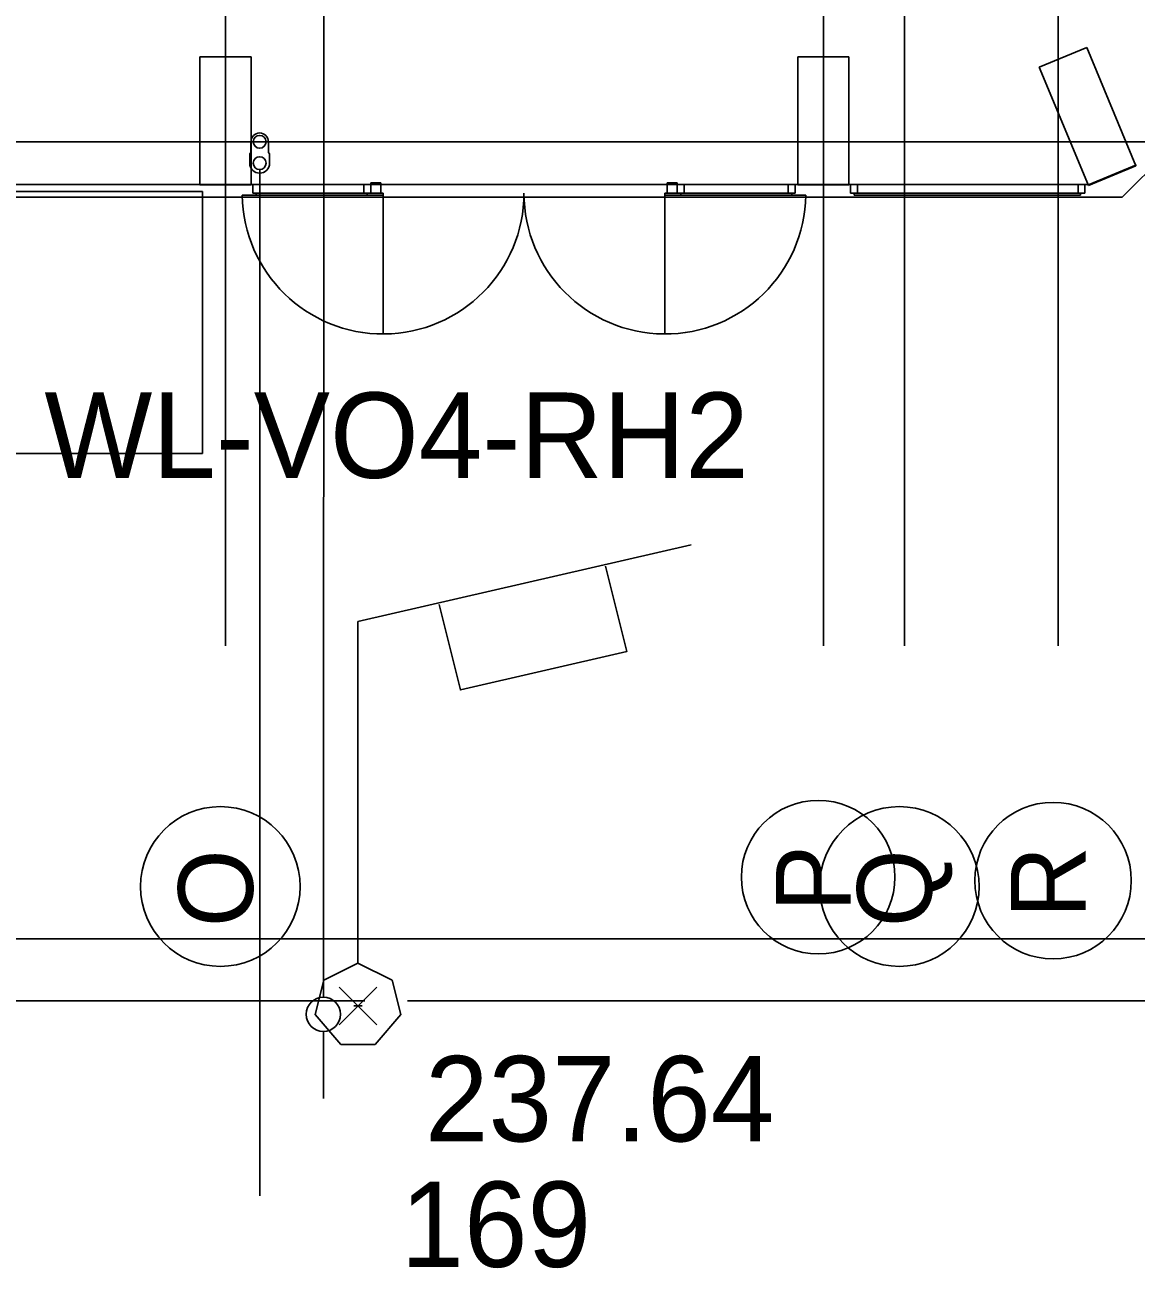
# Model space of a CAD drawing. Extents: x -264222 to -263592, y -1242345 to -1242048.
# Drawn here: x -263821.82 to -263808.81, y -1242253.99 to -1242239.44 of the extents above; entities that cross this region are included whole.
import ezdxf

# ---------------------------------------------------------------- set-up
doc = ezdxf.new("R2010")
doc.units = 0
for name, color, linetype in [('BOD_CISLO', 7, 'Continuous'), ('BOD_SYMBOL', 7, 'Continuous'), ('BOD_VYSKA', 7, 'Continuous'), ('HESCON_OSI_STAVBY_KFA', 7, 'Continuous'), ('KFA_2D_SITUACIA_DSP', 7, 'Continuous'), ('KFA_SO_62-1_VO_LAMPY_MERANE', 7, 'Continuous'), ('KFA_SO_62-1_VO_POPIS_LAMP_PROJEKT', 7, 'Continuous'), ('KFA_SO_62-1_VO_TRASA_KABLOV_PROJEKT', 7, 'Continuous')]:
    doc.layers.add(name, color=color, linetype=linetype)

msp = doc.modelspace()

# ---------------------------------------------------------------- linework, layer by layer
at = {"layer": 'BOD_SYMBOL'}
for p, q in [((-263818.138, -1242251.145), (-263817.696, -1242250.703)), ((-263817.696, -1242251.145), (-263818.138, -1242250.703))]:
    msp.add_line(p, q, dxfattribs=at)
at = {"layer": 'HESCON_OSI_STAVBY_KFA'}
for p, q in [((-263819.468, -1242083.237), (-263819.468, -1242246.707)), ((-263812.468, -1242083.237), (-263812.468, -1242246.707)), ((-263811.518, -1242083.237), (-263811.518, -1242246.707)), ((-263809.718, -1242083.237), (-263809.718, -1242246.707)), ((-263792.653, -1242240.807), (-263911.523, -1242240.807))]:
    msp.add_line(p, q, dxfattribs=at)
for centre, radius in [((-263819.528, -1242249.526), 0.935), ((-263812.528, -1242249.416), 0.899), ((-263811.578, -1242249.526), 0.935), ((-263809.778, -1242249.457), 0.916)]:
    msp.add_circle(centre, radius, dxfattribs=at)
at = {"layer": 'KFA_2D_SITUACIA_DSP'}
for p, q in [((-263818.318, -1242235.757), (-263818.321, -1242250.822)), ((-263809.939, -1242239.932), (-263809.384, -1242239.702)), ((-263809.384, -1242239.702), (-263808.81, -1242241.088)), ((-263819.768, -1242241.312), (-263819.768, -1242239.812)), ((-263819.768, -1242239.812), (-263819.168, -1242239.812)), ((-263819.168, -1242239.812), (-263819.168, -1242241.312)), ((-263812.768, -1242239.812), (-263812.768, -1242241.312)), ((-263812.168, -1242239.812), (-263812.768, -1242239.812)), ((-263812.168, -1242241.312), (-263812.168, -1242239.812)), ((-263809.365, -1242241.318), (-263809.939, -1242239.932)), ((-263819.171, -1242240.807), (-263819.171, -1242240.932)), ((-263818.965, -1242240.807), (-263818.965, -1242240.932)), ((-263819.171, -1242240.932), (-263819.185, -1242240.946)), ((-263819.185, -1242240.946), (-263819.185, -1242241.057)), ((-263818.965, -1242240.932), (-263818.951, -1242240.946)), ((-263818.951, -1242240.946), (-263818.951, -1242241.057)), ((-263818.951, -1242241.057), (-263818.951, -1242240.946)), ((-263819.068, -1242241.132), (-263819.068, -1242253.146)), ((-263808.81, -1242241.088), (-263809.365, -1242241.318)), ((-263808.8, -1242241.078), (-263809.355, -1242241.307)), ((-263894.581, -1242241.307), (-263809.355, -1242241.307)), ((-263819.168, -1242241.312), (-263819.768, -1242241.312)), ((-263819.068, -1242241.307), (-263819.148, -1242241.307)), ((-263819.148, -1242241.307), (-263819.148, -1242241.407)), ((-263819.068, -1242241.407), (-263819.068, -1242241.307)), ((-263817.848, -1242241.407), (-263817.848, -1242241.307)), ((-263817.848, -1242241.307), (-263817.768, -1242241.307)), ((-263817.648, -1242241.287), (-263817.768, -1242241.287)), ((-263817.768, -1242241.287), (-263817.768, -1242241.407)), ((-263817.768, -1242241.307), (-263817.768, -1242241.407)), ((-263817.648, -1242241.407), (-263817.648, -1242241.287)), ((-263814.298, -1242241.407), (-263814.298, -1242241.287)), ((-263814.298, -1242241.287), (-263814.178, -1242241.287)), ((-263814.178, -1242241.287), (-263814.178, -1242241.407)), ((-263814.098, -1242241.307), (-263814.178, -1242241.307)), ((-263814.178, -1242241.307), (-263814.178, -1242241.407)), ((-263814.098, -1242241.407), (-263814.098, -1242241.307)), ((-263812.878, -1242241.407), (-263812.878, -1242241.307)), ((-263812.878, -1242241.307), (-263812.798, -1242241.307)), ((-263812.798, -1242241.307), (-263812.798, -1242241.407)), ((-263812.768, -1242241.312), (-263812.168, -1242241.312)), ((-263812.068, -1242241.307), (-263812.148, -1242241.307)), ((-263812.148, -1242241.307), (-263812.148, -1242241.407)), ((-263812.068, -1242241.407), (-263812.068, -1242241.307)), ((-263809.405, -1242241.307), (-263809.485, -1242241.307)), ((-263809.485, -1242241.307), (-263809.485, -1242241.407)), ((-263809.405, -1242241.407), (-263809.405, -1242241.307)), ((-263819.738, -1242241.388), (-263827.188, -1242241.388)), ((-263819.738, -1242244.458), (-263819.738, -1242241.388)), ((-263819.273, -1242241.432), (-263817.623, -1242241.432)), ((-263819.148, -1242241.407), (-263819.108, -1242241.407)), ((-263819.108, -1242241.432), (-263819.108, -1242241.407)), ((-263819.108, -1242241.407), (-263817.808, -1242241.407)), ((-263819.108, -1242241.407), (-263819.068, -1242241.407)), ((-263817.808, -1242241.432), (-263819.108, -1242241.432)), ((-263817.808, -1242241.407), (-263817.848, -1242241.407)), ((-263817.808, -1242241.407), (-263817.808, -1242241.432)), ((-263817.768, -1242241.407), (-263817.808, -1242241.407)), ((-263817.768, -1242241.407), (-263817.648, -1242241.407)), ((-263817.648, -1242241.407), (-263817.623, -1242241.407)), ((-263817.623, -1242241.407), (-263817.623, -1242243.057)), ((-263814.298, -1242241.407), (-263814.323, -1242241.407)), ((-263814.323, -1242241.407), (-263814.323, -1242243.057)), ((-263812.673, -1242241.432), (-263814.323, -1242241.432)), ((-263814.178, -1242241.407), (-263814.298, -1242241.407)), ((-263814.178, -1242241.407), (-263814.138, -1242241.407)), ((-263812.838, -1242241.407), (-263814.138, -1242241.407)), ((-263814.138, -1242241.407), (-263814.138, -1242241.432)), ((-263814.138, -1242241.407), (-263814.098, -1242241.407)), ((-263814.138, -1242241.432), (-263812.838, -1242241.432)), ((-263812.838, -1242241.407), (-263812.878, -1242241.407)), ((-263812.838, -1242241.432), (-263812.838, -1242241.407)), ((-263812.798, -1242241.407), (-263812.838, -1242241.407)), ((-263812.148, -1242241.407), (-263812.108, -1242241.407)), ((-263812.108, -1242241.432), (-263812.108, -1242241.407)), ((-263812.108, -1242241.407), (-263809.458, -1242241.407)), ((-263812.108, -1242241.407), (-263812.068, -1242241.407)), ((-263809.458, -1242241.432), (-263812.108, -1242241.432)), ((-263809.485, -1242241.407), (-263809.445, -1242241.407)), ((-263809.458, -1242241.407), (-263809.458, -1242241.432)), ((-263809.445, -1242241.407), (-263809.405, -1242241.407)), ((-263827.188, -1242244.458), (-263819.738, -1242244.458)), ((-263924.143, -1242250.14), (-263788.143, -1242250.14)), ((-263818.322, -1242251.222), (-263818.322, -1242252.009))]:
    msp.add_line(p, q, dxfattribs=at)
msp.add_lwpolyline([(-263794.893, -1242227.382), (-263808.968, -1242241.457), (-263894.968, -1242241.457), (-263909.043, -1242227.382), (-263909.043, -1242196.333), (-263914.143, -1242196.333), (-263914.143, -1242132.433), (-263909.043, -1242132.433), (-263909.043, -1242101.382), (-263894.968, -1242087.307), (-263808.968, -1242087.307), (-263794.893, -1242101.382), (-263794.893, -1242227.382)], dxfattribs=at)
for centre, radius in [((-263819.068, -1242240.807), 0.075), ((-263819.068, -1242241.057), 0.075), ((-263818.322, -1242251.022), 0.2)]:
    msp.add_circle(centre, radius, dxfattribs=at)
for centre, radius, start, end in [((-263819.068, -1242240.807), 0.103, 360, 180), ((-263819.068, -1242241.057), 0.117, 180, 360), ((-263817.623, -1242241.407), 1.65, 180.8682, 0), ((-263814.323, -1242241.407), 1.65, 180, 359.1318)]:
    msp.add_arc(centre, radius, start, end, dxfattribs=at)
at = {"layer": 'KFA_SO_62-1_VO_LAMPY_MERANE'}
for p, q in [((-263817.967, -1242250.924), (-263817.867, -1242250.924)), ((-263817.917, -1242250.924), (-263817.917, -1242250.924))]:
    msp.add_line(p, q, dxfattribs=at)
for points in [[(-263817.917, -1242250.424), (-263818.317, -1242250.624), (-263818.417, -1242251.024), (-263818.117, -1242251.374), (-263817.717, -1242251.374), (-263817.417, -1242251.024), (-263817.517, -1242250.624), (-263817.917, -1242250.424), (-263817.917, -1242246.424), (-263814.017, -1242245.524)], [(-263815.017, -1242245.774), (-263814.767, -1242246.774), (-263816.717, -1242247.224), (-263816.967, -1242246.224)]]:
    msp.add_lwpolyline(points, dxfattribs=at)
at = {"layer": 'KFA_SO_62-1_VO_TRASA_KABLOV_PROJEKT'}
for p, q in [((-263817.838, -1242250.863), (-263836.838, -1242250.863)), ((-263798.338, -1242250.863), (-263817.338, -1242250.863))]:
    msp.add_line(p, q, dxfattribs=at)

# ---------------------------------------------------------------- texts
at = {"layer": 'BOD_CISLO'}
msp.add_text('169', height=1, dxfattribs=at).set_placement((-263817.419, -1242253.98))
at = {"layer": 'BOD_VYSKA'}
msp.add_text('237.64', height=1, dxfattribs=at).set_placement((-263817.132, -1242252.51))
at = {"layer": 'HESCON_OSI_STAVBY_KFA'}
for s, p in [('O', (-263819.147, -1242250.001)), ('P', (-263812.147, -1242249.824)), ('Q', (-263811.197, -1242250.001)), ('R', (-263809.397, -1242249.898))]:
    msp.add_text(s, height=0.875, rotation=90, dxfattribs=at).set_placement(p)
at = {"layer": 'KFA_SO_62-1_VO_POPIS_LAMP_PROJEKT'}
msp.add_text('WL-VO4-RH2', height=1, dxfattribs=at).set_placement((-263821.588, -1242244.742))

doc.saveas('drawing.dxf')
